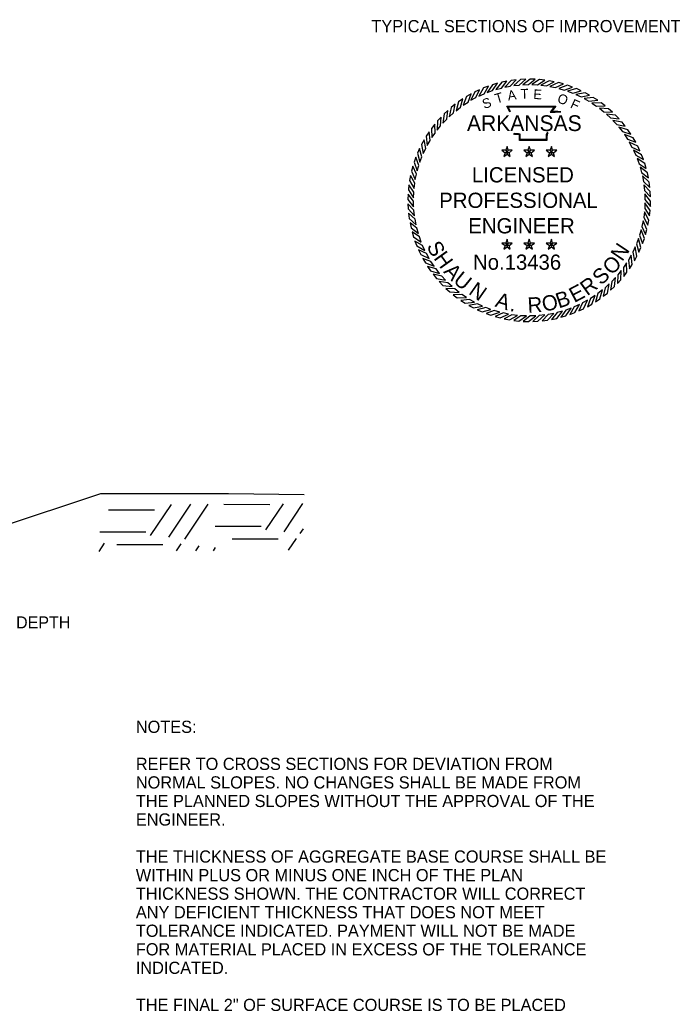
# Model space of a CAD drawing. Extents: x 1398183 to 1398373, y 1967240 to 1968889.
# Drawn here: x 1398303.93 to 1398336.4, y 1968683.76 to 1968732.55 of the extents above; entities that cross this region are included whole.
import ezdxf

# ---------------------------------------------------------------- set-up
doc = ezdxf.new("R2010")
doc.units = 0
for name, color, linetype in [('1', 7, 'Continuous'), ('19', 7, 'Continuous'), ('42', 7, 'Continuous'), ('9', 7, 'Continuous'), ('G-ANNO-SYMB', 7, 'Continuous')]:
    doc.layers.add(name, color=color, linetype=linetype)

msp = doc.modelspace()

# ---------------------------------------------------------------- linework, layer by layer
at = {"layer": '19'}
msp.add_line((1398298.544, 1968706.124), (1398307.911, 1968709.246), dxfattribs=at)
at = {"layer": '42'}
msp.add_lwpolyline([(1398307.911, 1968709.246), (1398314.197, 1968709.246), (1398317.913, 1968709.196)], dxfattribs=at)
at = {"layer": '9'}
for p, q in [((1398310.559, 1968708.418), (1398308.297, 1968708.424)), ((1398311.366, 1968708.708), (1398310.343, 1968707.174)), ((1398312.318, 1968708.714), (1398311.234, 1968707.086)), ((1398313.178, 1968708.718), (1398312.031, 1968706.998)), ((1398316.231, 1968708.691), (1398313.969, 1968708.697)), ((1398316.876, 1968708.739), (1398316.015, 1968707.447)), ((1398317.829, 1968708.744), (1398316.906, 1968707.359)), ((1398310.12, 1968707.34), (1398307.858, 1968707.346)), ((1398315.792, 1968707.613), (1398313.53, 1968707.619)), ((1398317.857, 1968707.502), (1398317.703, 1968707.271)), ((1398316.63, 1968706.987), (1398314.368, 1968706.993)), ((1398317.519, 1968707.029), (1398317.131, 1968706.446)), ((1398308.084, 1968706.791), (1398307.819, 1968706.394)), ((1398310.958, 1968706.714), (1398308.696, 1968706.72)), ((1398311.847, 1968706.756), (1398311.62, 1968706.415)), ((1398312.738, 1968706.668), (1398312.573, 1968706.421)), ((1398313.536, 1968706.58), (1398313.433, 1968706.426))]:
    msp.add_line(p, q, dxfattribs=at)
at = {"layer": 'G-ANNO-SYMB'}
for points in [[(1398326.975, 1968729.29), (1398326.735, 1968729.198), (1398326.51, 1968728.801), (1398326.763, 1968728.915)], [(1398327.422, 1968729.43), (1398327.176, 1968729.358), (1398326.92, 1968728.978), (1398327.181, 1968729.072)], [(1398327.879, 1968729.534), (1398327.628, 1968729.482), (1398327.343, 1968729.124), (1398327.61, 1968729.197)], [(1398328.342, 1968729.603), (1398328.088, 1968729.57), (1398327.776, 1968729.235), (1398328.048, 1968729.287)], [(1398328.81, 1968729.634), (1398328.553, 1968729.622), (1398328.216, 1968729.313), (1398328.492, 1968729.343)], [(1398329.278, 1968729.629), (1398329.021, 1968729.637), (1398328.661, 1968729.355), (1398328.938, 1968729.364)], [(1398329.745, 1968729.588), (1398329.489, 1968729.615), (1398329.108, 1968729.363), (1398329.385, 1968729.35)], [(1398330.206, 1968729.509), (1398329.954, 1968729.557), (1398329.554, 1968729.335), (1398329.829, 1968729.3)], [(1398330.661, 1968729.395), (1398330.413, 1968729.462), (1398329.997, 1968729.273), (1398330.268, 1968729.216)], [(1398331.105, 1968729.246), (1398330.863, 1968729.332), (1398330.433, 1968729.176), (1398330.699, 1968729.098)], [(1398326.121, 1968728.907), (1398325.898, 1968728.779), (1398325.738, 1968728.351), (1398325.97, 1968728.503)], [(1398326.54, 1968729.115), (1398326.309, 1968729.005), (1398326.115, 1968728.591), (1398326.358, 1968728.725)], [(1398331.535, 1968729.062), (1398331.301, 1968729.167), (1398330.861, 1968729.045), (1398331.12, 1968728.947)], [(1398331.951, 1968728.845), (1398331.725, 1968728.968), (1398331.277, 1968728.88), (1398331.527, 1968728.762)], [(1398325.337, 1968728.395), (1398325.137, 1968728.234), (1398325.046, 1968727.786), (1398325.251, 1968727.973)], [(1398325.719, 1968728.667), (1398325.507, 1968728.522), (1398325.381, 1968728.082), (1398325.6, 1968728.252)], [(1398332.347, 1968728.596), (1398332.132, 1968728.736), (1398331.678, 1968728.684), (1398331.919, 1968728.547)], [(1398332.723, 1968728.316), (1398332.52, 1968728.473), (1398332.063, 1968728.457), (1398332.292, 1968728.301)], [(1398324.977, 1968728.095), (1398324.791, 1968727.919), (1398324.735, 1968727.465), (1398324.925, 1968727.667)], [(1398333.076, 1968728.008), (1398332.886, 1968728.18), (1398332.429, 1968728.2), (1398332.646, 1968728.027)], [(1398333.404, 1968727.674), (1398333.228, 1968727.86), (1398332.774, 1968727.916), (1398332.976, 1968727.726)], [(1398324.335, 1968727.414), (1398324.178, 1968727.211), (1398324.194, 1968726.754), (1398324.35, 1968726.983)], [(1398324.643, 1968727.767), (1398324.471, 1968727.577), (1398324.451, 1968727.12), (1398324.624, 1968727.336)], [(1398333.704, 1968727.314), (1398333.543, 1968727.514), (1398333.095, 1968727.605), (1398333.282, 1968727.4)], [(1398324.055, 1968727.038), (1398323.915, 1968726.823), (1398323.967, 1968726.369), (1398324.104, 1968726.61)], [(1398333.976, 1968726.932), (1398333.831, 1968727.144), (1398333.391, 1968727.27), (1398333.561, 1968727.051)], [(1398334.216, 1968726.53), (1398334.088, 1968726.753), (1398333.66, 1968726.913), (1398333.812, 1968726.681)], [(1398323.806, 1968726.641), (1398323.683, 1968726.416), (1398323.771, 1968725.967), (1398323.888, 1968726.218)], [(1398334.424, 1968726.111), (1398334.314, 1968726.342), (1398333.9, 1968726.536), (1398334.034, 1968726.293)], [(1398323.589, 1968726.226), (1398323.484, 1968725.992), (1398323.606, 1968725.552), (1398323.704, 1968725.811)], [(1398327.889, 1968726.047), (1398327.828, 1968726.131), (1398327.63, 1968726.131), (1398327.79, 1968726.014)], [(1398327.889, 1968726.047), (1398327.79, 1968726.014), (1398327.729, 1968725.826), (1398327.889, 1968725.942)], [(1398327.889, 1968726.047), (1398327.95, 1968726.131), (1398327.889, 1968726.319), (1398327.828, 1968726.131)], [(1398327.889, 1968726.047), (1398327.988, 1968726.014), (1398328.148, 1968726.131), (1398327.95, 1968726.131)], [(1398327.889, 1968726.047), (1398327.889, 1968725.942), (1398328.049, 1968725.826), (1398327.988, 1968726.014)], [(1398328.98, 1968726.047), (1398328.919, 1968726.131), (1398328.721, 1968726.131), (1398328.881, 1968726.014)], [(1398328.98, 1968726.047), (1398328.881, 1968726.014), (1398328.82, 1968725.826), (1398328.98, 1968725.942)], [(1398328.98, 1968726.047), (1398329.041, 1968726.131), (1398328.98, 1968726.319), (1398328.919, 1968726.131)], [(1398328.98, 1968726.047), (1398329.079, 1968726.014), (1398329.239, 1968726.131), (1398329.041, 1968726.131)], [(1398328.98, 1968726.047), (1398328.98, 1968725.942), (1398329.14, 1968725.826), (1398329.079, 1968726.014)], [(1398330.071, 1968726.047), (1398330.01, 1968726.131), (1398329.812, 1968726.131), (1398329.972, 1968726.014)], [(1398330.071, 1968726.047), (1398329.972, 1968726.014), (1398329.911, 1968725.826), (1398330.071, 1968725.942)], [(1398330.071, 1968726.047), (1398330.132, 1968726.131), (1398330.071, 1968726.319), (1398330.01, 1968726.131)], [(1398330.071, 1968726.047), (1398330.17, 1968726.014), (1398330.33, 1968726.131), (1398330.132, 1968726.131)], [(1398330.071, 1968726.047), (1398330.071, 1968725.942), (1398330.231, 1968725.826), (1398330.17, 1968726.014)], [(1398334.599, 1968725.676), (1398334.508, 1968725.916), (1398334.11, 1968726.141), (1398334.224, 1968725.888)], [(1398323.405, 1968725.796), (1398323.319, 1968725.554), (1398323.475, 1968725.124), (1398323.553, 1968725.39)], [(1398334.739, 1968725.229), (1398334.667, 1968725.475), (1398334.288, 1968725.731), (1398334.382, 1968725.47)], [(1398323.141, 1968724.897), (1398323.094, 1968724.645), (1398323.316, 1968724.245), (1398323.35, 1968724.52)], [(1398323.256, 1968725.352), (1398323.189, 1968725.104), (1398323.378, 1968724.688), (1398323.434, 1968724.959)], [(1398334.843, 1968724.772), (1398334.791, 1968725.023), (1398334.433, 1968725.308), (1398334.506, 1968725.041)], [(1398323.063, 1968724.435), (1398323.036, 1968724.18), (1398323.288, 1968723.799), (1398323.301, 1968724.076)], [(1398334.912, 1968724.309), (1398334.879, 1968724.563), (1398334.544, 1968724.875), (1398334.596, 1968724.603)], [(1398334.944, 1968723.841), (1398334.931, 1968724.098), (1398334.622, 1968724.435), (1398334.652, 1968724.159)], [(1398323.022, 1968723.969), (1398323.014, 1968723.712), (1398323.296, 1968723.352), (1398323.287, 1968723.629)], [(1398334.939, 1968723.373), (1398334.946, 1968723.629), (1398334.664, 1968723.99), (1398334.673, 1968723.713)], [(1398323.017, 1968723.5), (1398323.029, 1968723.244), (1398323.338, 1968722.907), (1398323.308, 1968723.183)], [(1398334.897, 1968722.906), (1398334.924, 1968723.162), (1398334.672, 1968723.543), (1398334.659, 1968723.266)], [(1398323.048, 1968723.033), (1398323.081, 1968722.779), (1398323.416, 1968722.467), (1398323.364, 1968722.739)], [(1398334.819, 1968722.445), (1398334.866, 1968722.697), (1398334.644, 1968723.097), (1398334.61, 1968722.822)], [(1398323.117, 1968722.57), (1398323.169, 1968722.319), (1398323.527, 1968722.034), (1398323.454, 1968722.301)], [(1398334.704, 1968721.99), (1398334.771, 1968722.238), (1398334.582, 1968722.654), (1398334.526, 1968722.383)], [(1398323.221, 1968722.113), (1398323.293, 1968721.867), (1398323.672, 1968721.611), (1398323.579, 1968721.872)], [(1398334.555, 1968721.546), (1398334.641, 1968721.788), (1398334.485, 1968722.218), (1398334.407, 1968721.951)], [(1398323.361, 1968721.666), (1398323.452, 1968721.426), (1398323.85, 1968721.201), (1398323.736, 1968721.454)], [(1398327.889, 1968721.478), (1398327.828, 1968721.563), (1398327.63, 1968721.563), (1398327.79, 1968721.446)], [(1398327.889, 1968721.478), (1398327.79, 1968721.446), (1398327.729, 1968721.258), (1398327.889, 1968721.374)], [(1398327.889, 1968721.478), (1398327.95, 1968721.563), (1398327.889, 1968721.751), (1398327.828, 1968721.563)], [(1398327.889, 1968721.478), (1398327.988, 1968721.446), (1398328.148, 1968721.563), (1398327.95, 1968721.563)], [(1398327.889, 1968721.478), (1398327.889, 1968721.374), (1398328.049, 1968721.258), (1398327.988, 1968721.446)], [(1398328.98, 1968721.478), (1398328.919, 1968721.563), (1398328.721, 1968721.563), (1398328.881, 1968721.446)], [(1398328.98, 1968721.478), (1398328.881, 1968721.446), (1398328.82, 1968721.258), (1398328.98, 1968721.374)], [(1398328.98, 1968721.478), (1398329.041, 1968721.563), (1398328.98, 1968721.751), (1398328.919, 1968721.563)], [(1398328.98, 1968721.478), (1398329.079, 1968721.446), (1398329.239, 1968721.563), (1398329.041, 1968721.563)], [(1398328.98, 1968721.478), (1398328.98, 1968721.374), (1398329.14, 1968721.258), (1398329.079, 1968721.446)], [(1398330.071, 1968721.478), (1398330.01, 1968721.563), (1398329.812, 1968721.563), (1398329.972, 1968721.446)], [(1398330.071, 1968721.478), (1398329.972, 1968721.446), (1398329.911, 1968721.258), (1398330.071, 1968721.374)], [(1398330.071, 1968721.478), (1398330.132, 1968721.563), (1398330.071, 1968721.751), (1398330.01, 1968721.563)], [(1398330.071, 1968721.478), (1398330.17, 1968721.446), (1398330.33, 1968721.563), (1398330.132, 1968721.563)], [(1398330.071, 1968721.478), (1398330.071, 1968721.374), (1398330.231, 1968721.258), (1398330.17, 1968721.446)], [(1398334.371, 1968721.115), (1398334.476, 1968721.35), (1398334.354, 1968721.79), (1398334.256, 1968721.531)], [(1398323.536, 1968721.231), (1398323.646, 1968720.999), (1398324.06, 1968720.806), (1398323.926, 1968721.049)], [(1398334.154, 1968720.7), (1398334.277, 1968720.926), (1398334.19, 1968721.374), (1398334.072, 1968721.124)], [(1398323.744, 1968720.812), (1398323.872, 1968720.589), (1398324.3, 1968720.429), (1398324.148, 1968720.661)], [(1398333.625, 1968719.928), (1398333.782, 1968720.131), (1398333.766, 1968720.588), (1398333.61, 1968720.358)], [(1398333.905, 1968720.304), (1398334.045, 1968720.518), (1398333.993, 1968720.973), (1398333.856, 1968720.732)], [(1398323.984, 1968720.41), (1398324.129, 1968720.198), (1398324.569, 1968720.072), (1398324.399, 1968720.291)], [(1398324.256, 1968720.028), (1398324.417, 1968719.828), (1398324.865, 1968719.737), (1398324.678, 1968719.942)], [(1398333.317, 1968719.575), (1398333.49, 1968719.765), (1398333.509, 1968720.222), (1398333.336, 1968720.005)], [(1398324.556, 1968719.668), (1398324.732, 1968719.482), (1398325.186, 1968719.426), (1398324.984, 1968719.616)], [(1398332.623, 1968718.947), (1398332.823, 1968719.108), (1398332.914, 1968719.556), (1398332.709, 1968719.369)], [(1398332.983, 1968719.247), (1398333.169, 1968719.423), (1398333.225, 1968719.877), (1398333.035, 1968719.675)], [(1398324.884, 1968719.334), (1398325.074, 1968719.161), (1398325.531, 1968719.141), (1398325.314, 1968719.315)], [(1398325.237, 1968719.026), (1398325.44, 1968718.869), (1398325.897, 1968718.885), (1398325.668, 1968719.041)], [(1398332.241, 1968718.675), (1398332.453, 1968718.82), (1398332.579, 1968719.26), (1398332.36, 1968719.09)], [(1398325.613, 1968718.746), (1398325.828, 1968718.606), (1398326.282, 1968718.658), (1398326.041, 1968718.795)], [(1398326.009, 1968718.497), (1398326.235, 1968718.374), (1398326.684, 1968718.461), (1398326.433, 1968718.579)], [(1398330.985, 1968718.052), (1398331.225, 1968718.143), (1398331.45, 1968718.541), (1398331.197, 1968718.427)], [(1398331.42, 1968718.227), (1398331.651, 1968718.337), (1398331.845, 1968718.751), (1398331.602, 1968718.617)], [(1398331.839, 1968718.435), (1398332.062, 1968718.563), (1398332.222, 1968718.991), (1398331.99, 1968718.839)], [(1398326.425, 1968718.28), (1398326.659, 1968718.175), (1398327.099, 1968718.297), (1398326.84, 1968718.395)], [(1398326.855, 1968718.096), (1398327.097, 1968718.01), (1398327.527, 1968718.166), (1398327.261, 1968718.244)], [(1398327.299, 1968717.947), (1398327.547, 1968717.88), (1398327.963, 1968718.069), (1398327.692, 1968718.125)], [(1398329.618, 1968717.739), (1398329.872, 1968717.772), (1398330.184, 1968718.107), (1398329.912, 1968718.055)], [(1398330.081, 1968717.808), (1398330.332, 1968717.86), (1398330.617, 1968718.218), (1398330.35, 1968718.145)], [(1398330.538, 1968717.912), (1398330.784, 1968717.984), (1398331.04, 1968718.363), (1398330.779, 1968718.269)], [(1398327.754, 1968717.832), (1398328.006, 1968717.785), (1398328.406, 1968718.007), (1398328.131, 1968718.041)], [(1398328.216, 1968717.754), (1398328.471, 1968717.727), (1398328.852, 1968717.979), (1398328.575, 1968717.992)], [(1398328.682, 1968717.712), (1398328.939, 1968717.705), (1398329.299, 1968717.987), (1398329.022, 1968717.978)], [(1398329.151, 1968717.707), (1398329.407, 1968717.72), (1398329.744, 1968718.029), (1398329.468, 1968717.999)]]:
    msp.add_lwpolyline(points, close=True, dxfattribs=at)
for points in [[(1398328.024, 1968728.001), (1398327.885, 1968728.302), (1398330.292, 1968728.304), (1398330.09, 1968728.051), (1398330.254, 1968728.053), (1398330.391, 1968728.055), (1398330.527, 1968728.04)], [(1398328.059, 1968728.017), (1398327.945, 1968728.264), (1398330.212, 1968728.265), (1398330.011, 1968728.012), (1398330.254, 1968728.015), (1398330.389, 1968728.017), (1398330.523, 1968728.002)], [(1398329.912, 1968726.993), (1398329.871, 1968726.959), (1398329.858, 1968726.909), (1398329.844, 1968726.784), (1398329.844, 1968726.618), (1398328.501, 1968726.618), (1398328.501, 1968726.843), (1398328.501, 1968726.893), (1398328.446, 1968726.909), (1398328.255, 1968726.909), (1398328.221, 1968726.961)], [(1398329.888, 1968727.022), (1398329.838, 1968726.981), (1398329.82, 1968726.916), (1398329.806, 1968726.787), (1398329.806, 1968726.656), (1398328.539, 1968726.656), (1398328.539, 1968726.843), (1398328.539, 1968726.921), (1398328.452, 1968726.947), (1398328.276, 1968726.947), (1398328.253, 1968726.982)]]:
    msp.add_lwpolyline(points, dxfattribs=at)

# ---------------------------------------------------------------- texts
at = {"layer": '1'}
msp.add_text('TYPICAL SECTIONS OF IMPROVEMENT', height=0.6, dxfattribs=at).set_placement((1398321.219, 1968731.944))
at = {"layer": '19'}
msp.add_text('(CLASS 7) - VAR. COMPACTED DEPTH', height=0.59001, rotation=360, dxfattribs=at).set_placement((1398291.95, 1968702.603))
for s, p in [('NOTES:', (1398309.634, 1968697.46)), ('REFER TO CROSS SECTIONS FOR DEVIATION FROM', (1398309.634, 1968695.635)), ('NORMAL SLOPES. NO CHANGES SHALL BE MADE FROM ', (1398309.634, 1968694.723)), ('THE PLANNED SLOPES WITHOUT THE APPROVAL OF THE', (1398309.634, 1968693.81)), ('ENGINEER.', (1398309.634, 1968692.898)), ('THE THICKNESS OF AGGREGATE BASE COURSE SHALL BE', (1398309.634, 1968691.073)), ('WITHIN PLUS OR MINUS ONE INCH OF THE PLAN ', (1398309.634, 1968690.16)), ('THICKNESS SHOWN. THE CONTRACTOR WILL CORRECT', (1398309.634, 1968689.248)), ('ANY DEFICIENT THICKNESS THAT DOES NOT MEET', (1398309.634, 1968688.335)), ('TOLERANCE INDICATED. PAYMENT WILL NOT BE MADE', (1398309.634, 1968687.423)), ('FOR MATERIAL PLACED IN EXCESS OF THE TOLERANCE', (1398309.634, 1968686.51)), ('INDICATED.', (1398309.634, 1968685.598)), ('THE FINAL 2" OF SURFACE COURSE IS TO BE PLACED', (1398309.634, 1968683.773))]:
    msp.add_text(s, height=0.6, dxfattribs=at).set_placement(p)
at = {"layer": 'G-ANNO-SYMB'}
for s, height, rotation, p in [('T', 0.475, 16.9015, (1398327.375, 1968728.43)), ('A', 0.475, 8.6788, (1398327.951, 1968728.58)), ('T', 0.475, 1.4789, (1398328.564, 1968728.675)), ('E', 0.475, 356.672, (1398329.171, 1968728.66)), ('O', 0.475, 341.2218, (1398330.324, 1968728.497)), ('S', 0.475, 19.7726, (1398326.771, 1968728.159)), ('F', 0.475, 335.3628, (1398330.964, 1968728.247)), ('S', 0.75, 298.1636, (1398323.912, 1968721.411)), ('N', 0.75, 56.1007, (1398333.554, 1968720.628)), ('H', 0.75, 305.619, (1398324.254, 1968720.823)), ('O', 0.75, 44.7757, (1398333.033, 1968719.952)), ('A', 0.75, 313.4472, (1398324.73, 1968720.139)), ('U', 0.75, 320.9026, (1398325.198, 1968719.65)), ('S', 0.75, 43.4878, (1398332.518, 1968719.455)), ('N', 0.75, 324.9326, (1398325.954, 1968719.091)), ('E', 0.75, 27.8315, (1398331.194, 1968718.613)), ('R', 0.75, 35.6597, (1398331.828, 1968718.945)), ('A', 0.75, 343.0991, (1398327.261, 1968718.448)), ('O', 0.75, 11.4296, (1398329.685, 1968718.183)), ('B', 0.75, 18.885, (1398330.437, 1968718.342)), ('R', 0.75, 3.2287, (1398328.918, 1968718.134)), ('.', 0.75, 351.3, (1398327.998, 1968718.229))]:
    msp.add_text(s, height=height, rotation=rotation, dxfattribs=at).set_placement(p)
for s, height, p in [('ARKANSAS', 0.7747, (1398325.918, 1968727.079)), ('LICENSED', 0.75, (1398326.159, 1968724.55)), ('PROFESSIONAL', 0.75, (1398324.551, 1968723.296)), ('ENGINEER', 0.75, (1398325.98, 1968722.042)), ('No.13436', 0.747, (1398326.217, 1968720.254))]:
    msp.add_text(s, height=height, dxfattribs=at).set_placement(p)

doc.saveas('drawing.dxf')
